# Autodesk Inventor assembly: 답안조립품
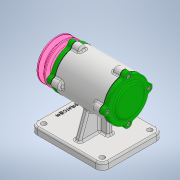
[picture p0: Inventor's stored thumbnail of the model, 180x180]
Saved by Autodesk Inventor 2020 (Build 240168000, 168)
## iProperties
Created: 2022-11
Part Number: 답안조립품
Document SubType Name: Assembly
Designer: owner
Author: owner
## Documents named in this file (12)
- C:\Users\owner\Desktop\721108V1006\답안조립품.iam
- C:\Users\owner\Desktop\721108V1006\본체.ipt
- C:\Users\owner\Desktop\721108V1006\V-벨트풀리.ipt
- C:\Users\owner\Desktop\721108V1006\개스킷.ipt
- C:\Users\owner\Desktop\721108V1006\너트 M12 x 1.25.ipt
- C:\Users\owner\Desktop\721108V1006\뒤커버.ipt
- C:\Users\owner\Desktop\721108V1006\베어링 6204.ipt
- C:\Users\owner\Desktop\721108V1006\볼트 M4 x 12.ipt
- C:\Users\owner\Desktop\721108V1006\앞커버.ipt
- C:\Users\owner\Desktop\721108V1006\오일 실.ipt
- C:\Users\owner\Desktop\721108V1006\축.ipt
- C:\Users\owner\Desktop\721108V1006\키 4 x 4.ipt
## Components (8 placed, 6 different names)
1. V-벨트풀리:1 — 각도:1
2. 개스킷:1
3. KS B 1012 클래스 1 일반 - 미터 M12x1.25:1 — 각도:1
4. KS B 2023 6204 - 20 x 47 x 14:1
5. KS B 2804 D D - 20 32 8:1
6. KS B 1311 (I) 4 x 4 x 12:1
7. KS B 2023 6204 - 20 x 47 x 14:2
8. 개스킷:2
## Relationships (1: Angle 1)
- 각도:1 [Angle]: V-벨트풀리:1 ↔ KS B 1012 클래스 1 일반 - 미터 M12x1.25:1
